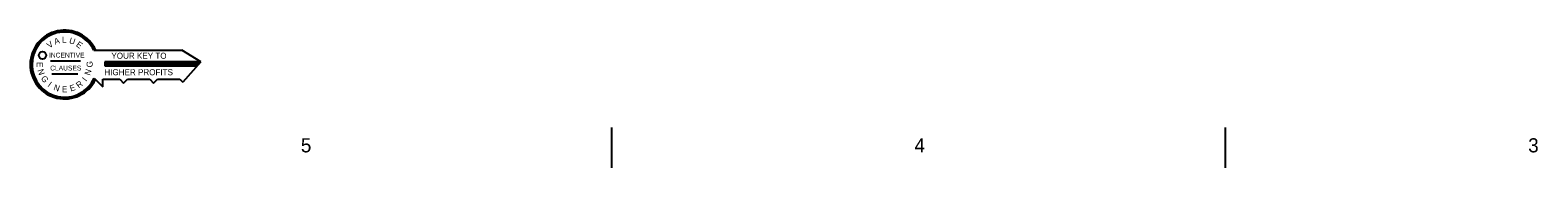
# Model space of a CAD drawing. Extents: x 18232 to 22378, y 12454 to 22381.
# Drawn here: x 22363.71 to 22365.272, y 22370.035 to 22370.178 of the extents above; entities that cross this region are included whole.
import ezdxf

# ---------------------------------------------------------------- set-up
doc = ezdxf.new("R2010")
doc.units = 0
doc.layers.add('Level 1', color=7, linetype='Continuous')

msp = doc.modelspace()

# ---------------------------------------------------------------- linework, layer by layer
at = {"layer": 'Level 1'}
for p, q in [((22363.7313, 22370.146), (22363.7624, 22370.146)), ((22363.7763, 22370.157), (22363.8673, 22370.157)), ((22363.8872, 22370.1452), (22363.8673, 22370.157)), ((22363.7329, 22370.1328), (22363.7599, 22370.1328)), ((22363.8869, 22370.1449), (22363.7878, 22370.1449)), ((22363.7878, 22370.1449), (22363.7878, 22370.141)), ((22363.8859, 22370.1438), (22363.7878, 22370.1438)), ((22363.8851, 22370.1428), (22363.7878, 22370.1428)), ((22363.8841, 22370.1418), (22363.7878, 22370.1418)), ((22363.7878, 22370.141), (22363.8834, 22370.141)), ((22363.8872, 22370.1452), (22363.8683, 22370.124)), ((22363.7767, 22370.1282), (22363.7858, 22370.1192)), ((22363.7858, 22370.1192), (22363.7858, 22370.127)), ((22363.7858, 22370.127), (22363.8033, 22370.127)), ((22363.8033, 22370.127), (22363.8072, 22370.1231)), ((22363.8072, 22370.1231), (22363.8111, 22370.127)), ((22363.8111, 22370.127), (22363.8343, 22370.127)), ((22363.8343, 22370.127), (22363.8382, 22370.1231)), ((22363.8382, 22370.1231), (22363.8421, 22370.127)), ((22363.8421, 22370.127), (22363.8653, 22370.127)), ((22363.8653, 22370.127), (22363.8683, 22370.124)), ((22364.3125, 22370.0771), (22364.3125, 22370.0354)), ((22364.9479, 22370.0771), (22364.9479, 22370.0354))]:
    msp.add_line(p, q, dxfattribs=at)
msp.add_circle((22363.7232, 22370.1518), 0.00384, dxfattribs=at)
for radius, start, end in [(0.0356, 24.569, 334.4243), (0.0346, 25.3095, 334.4522), (0.0337, 26.0896, 335.5943)]:
    msp.add_arc((22363.746, 22370.1422), radius, start, end, dxfattribs=at)

# ---------------------------------------------------------------- texts
for s, rotation, p in [('V', 35.9204, (22363.7304, 22370.1587)), ('A', 18.0731, (22363.7363, 22370.1627)), ('U', 342.1107, (22363.7502, 22370.1645)), ('E', 323.9298, (22363.7573, 22370.1617)), ('E', 270, (22363.7172, 22370.1449)), ('N', 288.0821, (22363.7179, 22370.1364)), ('G', 306.0537, (22363.7211, 22370.1279)), ('N', 71.9179, (22363.7723, 22370.1305)), ('G', 90, (22363.7751, 22370.1393)), ('I', 323.5836, (22363.728, 22370.12)), ('N', 341.9179, (22363.7341, 22370.116)), ('E', 18.2241, (22363.7525, 22370.1143)), ('R', 36.2206, (22363.7607, 22370.1175)), ('I', 53.5836, (22363.7684, 22370.1243))]:
    msp.add_text(s, height=0.00625, rotation=rotation, dxfattribs=at).set_placement(p)
for s, height, p in [('L', 0.00625, (22363.7434, 22370.1647)), ('INCENTIVE', 0.005, (22363.7299, 22370.1495)), ('YOUR KEY TO', 0.00625, (22363.7945, 22370.1482)), ('CLAUSES', 0.005, (22363.7311, 22370.1361)), ('HIGHER PROFITS', 0.00625, (22363.7872, 22370.1312)), ('E', 0.00625, (22363.7433, 22370.1136)), ('5', 0.0146, (22363.9907, 22370.0514)), ('4', 0.0146, (22364.6261, 22370.0514)), ('3', 0.0146, (22365.2615, 22370.0514))]:
    msp.add_text(s, height=height, dxfattribs=at).set_placement(p)

doc.saveas('drawing.dxf')
